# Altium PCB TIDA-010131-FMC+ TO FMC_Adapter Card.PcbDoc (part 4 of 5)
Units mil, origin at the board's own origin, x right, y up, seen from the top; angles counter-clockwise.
Board outline 2874.02 x 2362.2 mil, 12 copper layers (L1_Top Layer, L2_GND, L3_GND, L4_Signal layer1, L5_GND, L6_Signal Layer2, L7_GND, L8_Signal Layer3, L9_GND, L10_Signal Layer4, L11_GND, L12_Bottom Layer), stack 65.6 mil thick; 64 components, 219 nets, 2252 pads, 791 vias.
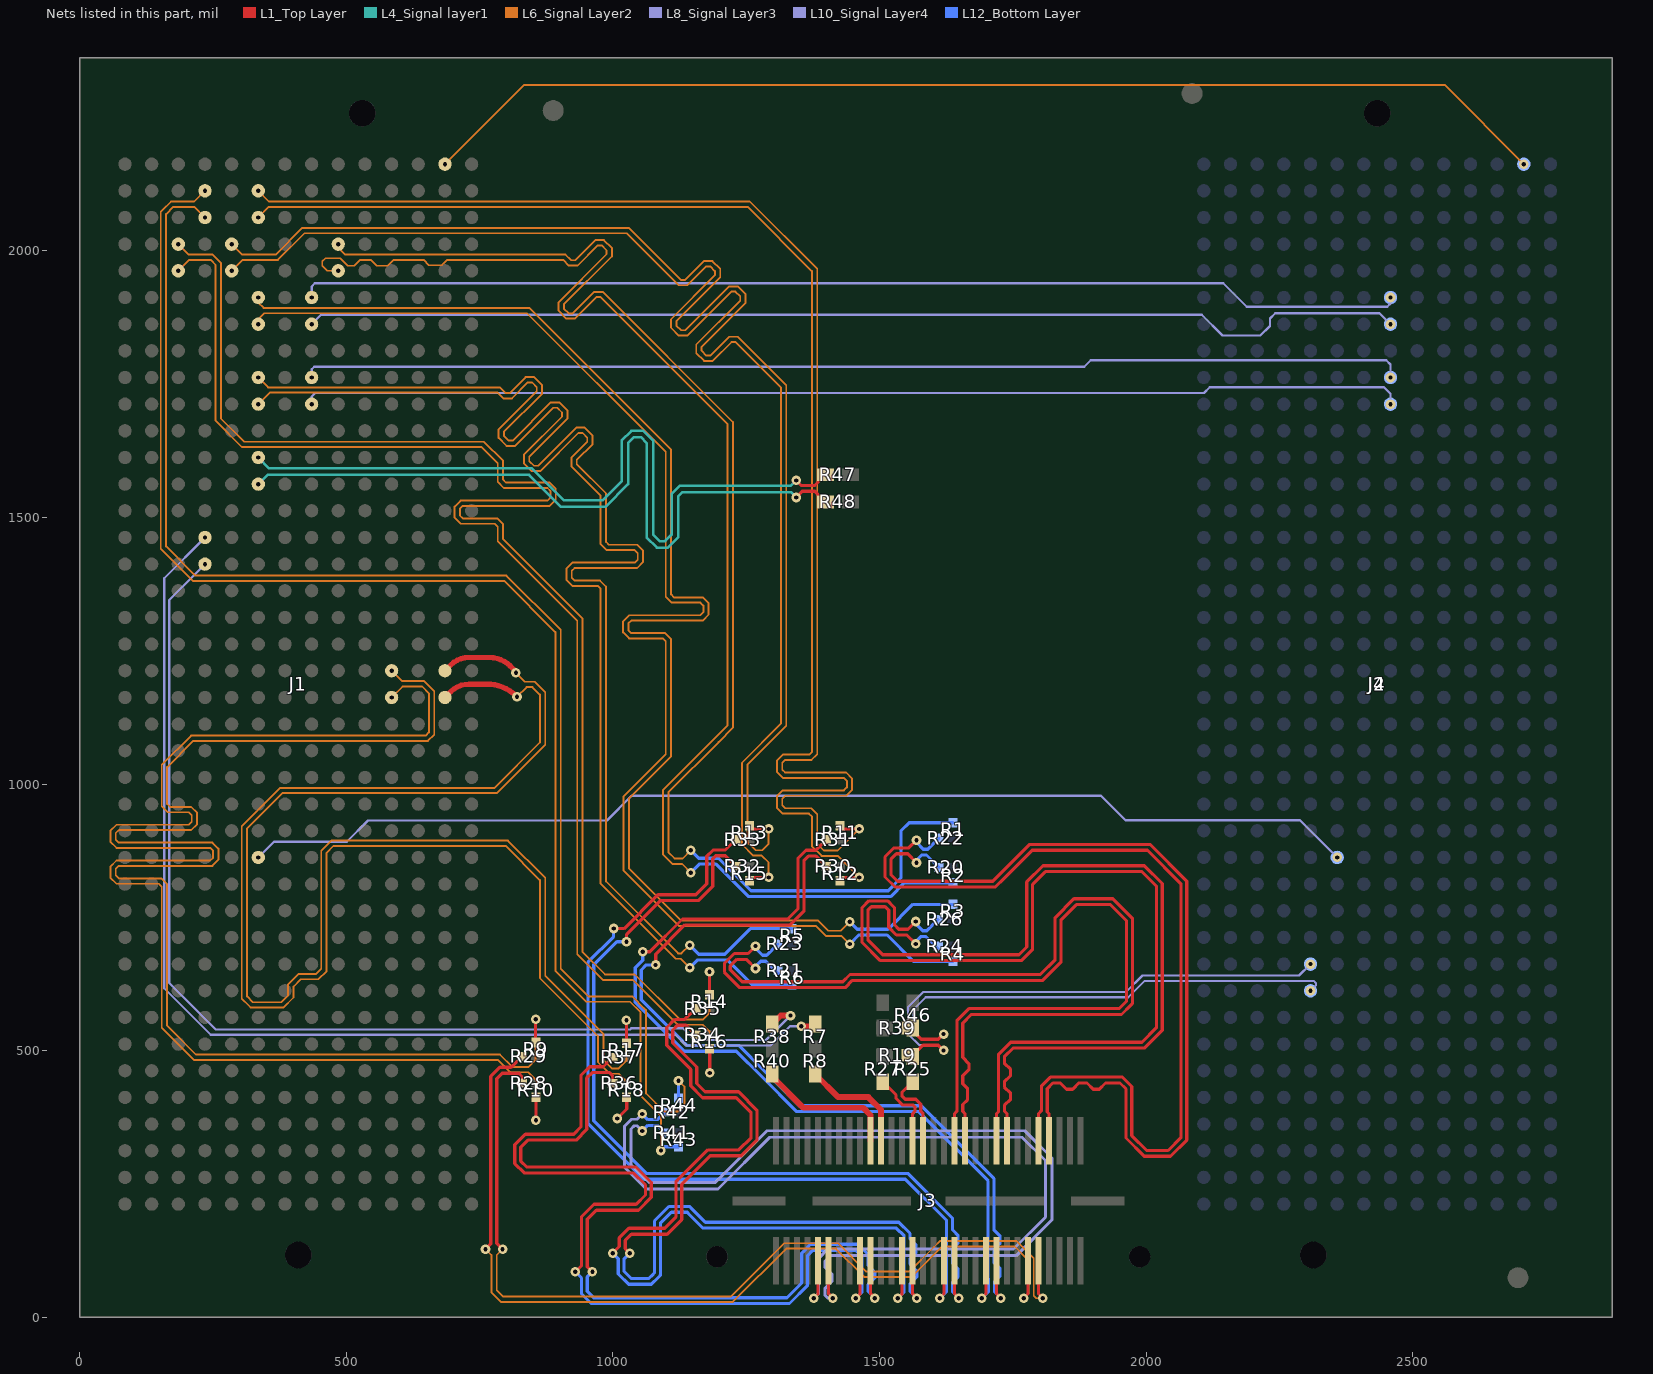
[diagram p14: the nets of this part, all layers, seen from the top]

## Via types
v1: diameter 18, hole 8, L1_Top Layer to L12_Bottom Layer, 791 vias

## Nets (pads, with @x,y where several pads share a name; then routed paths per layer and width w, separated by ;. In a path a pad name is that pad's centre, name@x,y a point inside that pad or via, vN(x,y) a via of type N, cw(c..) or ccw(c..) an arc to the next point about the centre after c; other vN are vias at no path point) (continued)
NetJ1_B20: J1.B20 R9.2 | length 2677.1
  L1_Top Layer w6: v1(855,559) 855,515.98 R9.2@855.49,515.48
  L6_Signal Layer2 w3.5: v1(585,1212.5) 604.5,1193 646.14,1193 665,1174.14 665,1092.86 653.14,1081 213,1081 164,1032 164,962.7 169.45,957.25 208.77,957.25 220.07,945.95 220.07,925.05 208.77,913.75 73.24,913.75 67.79,908.3 67.79,895.7 73.24,890.25 248.9,890.25 260.21,878.95 260.21,858.05 248.9,846.75 73.24,846.75 67.79,841.3 67.79,828.7 73.24,823.25 152.7,823.25 164,811.95 164,547 218,493 788,493 811.25,469.75 842,469.75 855,482.75 v1(855,559)
NetJ1_B21: J1.B21 R10.2 | length 2678.1
  L1_Top Layer w6: R10.2@855.01,413.01 R10.2@855.5,412.52 v1(855.5,369.49)
  L6_Signal Layer2 w3.5: v1(585,1162.5) 605.5,1183 642,1183 655,1170 655,1097 649,1091 208.86,1091 154,1036.14 154,958.55 165.3,947.25 204.63,947.25 210.07,941.8 210.07,929.2 204.63,923.75 69.1,923.75 57.79,912.45 57.79,891.55 69.1,880.25 244.76,880.25 250.21,874.8 250.21,862.2 244.76,856.75 69.1,856.75 57.79,845.45 57.79,824.55 69.1,813.25 148.55,813.25 154,807.8 154,542.86 213.86,483 783.86,483 807.11,459.75 841,459.75 855.5,445.25 v1(855.5,369.49)
NetJ1_D4: J1.D4 R1.2 | length 2678.3
  L6_Signal Layer2 w3.5: v1(485,2012.5) 485,2006 498,1993 911,1993 921.69,1982.31 929.4,1982.3 967.18,2020.09 983.17,2020.09 997.94,2005.32 997.94,1989.33 908,1899.39 908,1891.69 916.92,1882.77 924.62,1882.77 964.93,1923.08 980.92,1923.08 1225,1679 1225,1105.86 1198,1078.86 1104,984.86 1104,872 1115.5,860.5 1130.5,860.5 v1(1146,876)
  L12_Bottom Layer w6: v1(1146,876) 1161,861 1198,861 1258.94,800.06 1516.06,800.06 1540,824 1540,912 1555.52,927.52 R1.2@1637.75,927.52
NetJ1_D5: J1.D5 R2.2 | length 2675.8
  L6_Signal Layer2 w3.5: v1(485,1962.5) 464.5,1962.5 455,1972 455,1980 461,1986 489,1986 503,1972 515,1972 526,1983 546,1983 557,1972 578,1972 589,1983 645,1983 655,1973 679,1973 689,1983 906.86,1983 917.55,1972.31 933.54,1972.3 971.32,2010.09 979.02,2010.09 987.94,2001.17 987.94,1993.47 898,1903.53 898,1887.55 912.77,1872.77 928.76,1872.77 969.07,1913.08 976.77,1913.08 1215,1674.86 1215,1110 1094,989 1094,867.86 1111.36,850.5 1129.5,850.5 v1(1146,834)
  L12_Bottom Layer w6: v1(1146,834) 1162,850 1193.44,850 1254.39,789.06 1520.61,789.06 1546.6,815.04 R2.2@1637.75,815.04
NetJ1_G2: J1.G2 R11.1 | length 2680.8
  L1_Top Layer w6: R11.1@1426,922 1431.98,916.02 v1(1462.01,916.02)
  L6_Signal Layer2 w3.5: v1(335,2112.5) 355,2092.5 1256.64,2092.5 1383,1966.14 1383,1055.93 1372.32,1045.25 1322.87,1045.25 1317.42,1039.8 1317.42,1027.2 1322.87,1021.75 1437.27,1021.75 1448.58,1010.45 1448.58,989.55 1437.27,978.25 1322.87,978.25 1317.42,972.8 1317.42,960.2 1322.87,954.75 1371.7,954.75 1383,943.45 1383,888.02 1395.5,875.52 1421.51,875.52 v1(1462.01,916.02)
NetJ1_G3: J1.G3 R12.1 | length 2680.8
  L1_Top Layer w6: R12.1@1426,819.03 1431.98,825.02 v1(1462.01,825.02)
  L6_Signal Layer2 w3.5: v1(335,2062.5) 355,2082.5 1252.5,2082.5 1373,1962 1373,1060.07 1368.18,1055.25 1318.73,1055.25 1307.42,1043.95 1307.42,1023.05 1318.73,1011.75 1433.13,1011.75 1438.58,1006.3 1438.58,993.7 1433.13,988.25 1318.73,988.25 1307.42,976.95 1307.42,956.05 1318.73,944.75 1367.55,944.75 1373,939.3 1373,883.87 1391.36,865.52 1421.51,865.52 v1(1462.01,825.02)
NetJ1_G6: J1.G6 R3.1 | length 2675.3
  L6_Signal Layer2 w3.5: v1(335,1912.5) 335,1903 345,1893 843,1893 1109,1627 1109,1355.7 1114.45,1350.25 1168.2,1350.25 1179.5,1338.95 1179.5,1318.05 1168.2,1306.75 1034.45,1306.75 1029,1301.3 1029,1288.7 1034.45,1283.25 1097.7,1283.25 1109,1271.95 1109,1051.86 1030,972.86 1030,841.94 1127.94,744 1384.83,744 1403.83,725 1426.9,725 v1(1443.95,742.05)
  L12_Bottom Layer w6: v1(1443.95,742.05) 1458,728 1516,728 1562.49,774.49 R3.1@1637.6,774.49
NetJ1_G7: J1.G7 R4.1 | length 2677.3
  L6_Signal Layer2 w3.5: v1(335,1862.5) 335,1872 346,1883 838.86,1883 1099,1622.86 1099,1351.55 1110.3,1340.25 1164.06,1340.25 1169.5,1334.81 1169.5,1322.19 1164.06,1316.75 1030.3,1316.75 1019,1305.45 1019,1284.55 1030.3,1273.25 1093.55,1273.25 1099,1267.8 1099,1056 1020,977 1020,837.8 1123.8,734 1380.69,734 1399.69,715 1429,715 v1(1443.95,700.05)
  L12_Bottom Layer w6: v1(1443.95,700.05) 1460.9,717 1514,717 1563.39,667.61 R4.1@1637.6,667.61
NetJ1_G9: J1.G9 R5.1 | length 2676.2
  L6_Signal Layer2 w3.5: v1(335,1762.5) 353.5,1744 788.14,1744 798.84,1733.31 806.54,1733.3 836.35,1763.12 852.34,1763.12 867.11,1748.34 867.11,1732.36 795.64,1660.89 795.64,1653.19 804.56,1644.27 812.26,1644.27 883.73,1715.74 899.71,1715.74 914.49,1700.97 914.49,1684.98 843.02,1613.51 843.02,1605.81 851.93,1596.9 859.63,1596.9 931.1,1668.37 947.09,1668.37 961.86,1653.59 961.86,1637.61 932.05,1607.79 932.05,1600.09 987,1545.14 987,1454.2 992.45,1448.75 1045.15,1448.75 1056.45,1437.45 1056.45,1416.55 1045.15,1405.25 928.1,1405.25 922.65,1399.8 922.65,1387.2 928.1,1381.75 975.7,1381.75 987,1370.45 987,817.56 1122.06,682.5 1128.5,682.5 v1(1144,698)
  L12_Bottom Layer w6: v1(1144,698) 1161,681 1209.85,681 1257.82,728.97 R5.1@1335.93,728.97
NetJ1_G10: J1.G10 R6.1 | length 2676.1
  L6_Signal Layer2 w3.5: v1(335,1712.5) 356.5,1734 784,1734 794.69,1723.31 810.68,1723.3 840.49,1753.12 848.2,1753.12 857.11,1744.2 857.11,1736.5 785.64,1665.03 785.64,1649.05 800.41,1634.27 816.4,1634.27 887.87,1705.74 895.57,1705.74 904.49,1696.83 904.49,1689.12 833.02,1617.66 833.02,1601.67 847.79,1586.9 863.78,1586.9 935.25,1658.37 942.95,1658.37 951.86,1649.45 951.86,1641.75 922.05,1611.94 922.05,1595.95 977,1541 977,1450.05 988.3,1438.75 1041.01,1438.75 1046.45,1433.3 1046.45,1420.7 1041.01,1415.25 923.96,1415.25 912.65,1403.95 912.65,1383.05 923.96,1371.75 971.55,1371.75 977,1366.3 977,813.41 1117.91,672.5 1127.5,672.5 v1(1144,656)
  L12_Bottom Layer w6: v1(1144,656) 1158,670 1214.4,670 1214.7,670.3 1260.97,624.03 R6.1@1335.93,624.03
NetJ1_G12: J1.G12 R47.1 | length 1489.1
  L1_Top Layer w6: v1(1343.5,1569.5) 1353,1560 1378.38,1560 R47.1@1398.38,1580
  L4_Signal layer1 w4.9: v1(335,1612.5) 355.5,1592 848,1592 908,1532 980.74,1532 1016.45,1567.71 1016.45,1644.26 1034.69,1662.5 1057.11,1662.5 1075.35,1644.26 1075.35,1467.71 1087.56,1455.5 1098.04,1455.5 1110.25,1467.71 1110.25,1544.26 1125.49,1559.5 1333.5,1559.5 v1(1343.5,1569.5)
NetJ1_G13: J1.G13 R48.1 | length 1488.6
  L1_Top Layer w6: v1(1343.49,1537.5) 1354.99,1549 1378.38,1549 R48.1@1398.38,1529
  L4_Signal layer1 w4.9: v1(335,1562.5) 352.5,1580 843.03,1580 903.03,1520 985.71,1520 1028.45,1562.74 1028.45,1639.29 1039.66,1650.5 1052.14,1650.5 1063.35,1639.29 1063.35,1462.74 1082.59,1443.5 1103.01,1443.5 1122.25,1462.74 1122.25,1539.29 1130.46,1547.5 1333.49,1547.5 v1(1343.49,1537.5)
NetJ1_H4: J1.H4 R13.2 | length 2680
  L1_Top Layer w6: R13.2@1255.99,921.98 1261.98,916 v1(1292,916)
  L6_Signal Layer2 w3.5: v1(285,2012.5) 304.5,1993 367.44,1993 417.44,2043 1030,2043 1127.53,1945.47 1135.23,1945.47 1170.53,1980.77 1186.51,1980.77 1201.29,1966 1201.29,1950.01 1118.85,1867.57 1118.85,1859.87 1127.76,1850.95 1135.46,1850.95 1217.9,1933.39 1233.89,1933.39 1248.66,1918.62 1248.66,1902.63 1166.22,1820.19 1166.22,1812.49 1175.14,1803.58 1182.84,1803.58 1218.14,1838.88 1234.12,1838.88 1325,1748 1325,1109 1252,1036 1252,891.39 1267.39,876 1280,876 1292,888 v1(1292,916)
NetJ1_H5: J1.H5 R15.2 | length 2680.8
  L1_Top Layer w6: R15.2@1255.99,819.02 1261.98,825 v1(1292,825)
  L6_Signal Layer2 w3.5: v1(285,1962.5) 305.5,1983 371.59,1983 421.59,2033 1025.86,2033 1123.39,1935.47 1139.37,1935.47 1174.67,1970.77 1182.37,1970.77 1191.29,1961.85 1191.29,1954.15 1108.85,1871.71 1108.85,1855.73 1123.62,1840.95 1139.61,1840.95 1222.05,1923.39 1229.75,1923.39 1238.66,1914.48 1238.66,1906.78 1156.22,1824.34 1156.22,1808.35 1171,1793.58 1186.98,1793.58 1222.28,1828.88 1229.98,1828.88 1315,1743.86 1315,1113.14 1242,1040.14 1242,887.24 1263.24,866 1279,866 1292,853 v1(1292,825)
NetJ1_J2: J1.J2 R43.1 | length 2673.8
  L6_Signal Layer2 w3.5: v1(235,2112.5) 215,2092.5 171.36,2092.5 154.93,2076.07 152,2073.14 152,1441.5 212.5,1381 796,1381 892,1285 892,649.86 949.86,592 1032,592 1052,572 1052,415.86 1090,377.86 v1(1090,313)
  L12_Bottom Layer w6: v1(1090,313) 1097.02,320.02 R43.1@1122.98,320.02
NetJ1_J3: J1.J3 R44.1 | length 2673.8
  L6_Signal Layer2 w3.5: v1(235,2062.5) 215,2082.5 175.5,2082.5 162,2069 162,1445.64 216.64,1391 800.14,1391 902,1289.14 902,654 954,602 1036.14,602 1059.07,579.07 1062,576.14 1062,420 1096,386 1123,386 1134,397 1134,433 v1(1123,444)
  L12_Bottom Layer w6: R44.1@1122.98,410.98 v1(1123,444)
NetJ1_J15: J1.J15 R7.1 | length 2158.3
  L1_Top Layer w11: v1(1353,546) 1374.76,546 R7.1@1379,550.24
  L8_Signal Layer3 w4.25: v1(235,1462.5) 158.63,1386.13 158.63,617.37 246,530 1117,530 1137,510 1296,510 1332,546 v1(1353,546)
NetJ1_J16: J1.J16 R38.1 | length 2084
  L1_Top Layer w11: R38.1@1299,550.24 1314.76,566 v1(1333,566)
  L8_Signal Layer3 w4.25: v1(235,1412.5) 167.88,1345.38 167.88,627.12 255.15,539.85 1032.34,539.85 1034.49,542 1131,542 1153,520 1287,520 v1(1333,566)
NetJ1_K4: J1.K4 R14.2 | length 2676.7
  L1_Top Layer w6: R14.2@1181,604.98 v1(1181,648.01)
  L6_Signal Layer2 w3.5: v1(185,2012.5) 204.5,1993 249.56,1993 265,1977.56 265,1685.56 308.56,1642 758.14,1642 794,1606.14 794,1570.7 799.45,1565.25 881.43,1565.25 892.74,1553.95 892.74,1533.05 881.43,1521.75 718.46,1521.75 713.01,1516.3 713.01,1503.7 718.46,1498.25 782.7,1498.25 794,1486.95 794,1459.14 943,1310.14 943,685.14 985.14,643 1041,643 1125.25,558.75 1169,558.75 1181,570.75 v1(1181,648.01)
NetJ1_K5: J1.K5 R16.2 | length 2677.7
  L1_Top Layer w6: v1(1181.5,458.5) R16.2@1181.5,501.52
  L6_Signal Layer2 w3.5: v1(185,1962.5) 205.5,1983 245.41,1983 255,1973.41 255,1681.41 304.41,1632 754,1632 784,1602 784,1566.55 795.3,1555.25 877.29,1555.25 882.74,1549.8 882.74,1537.2 877.29,1531.75 714.32,1531.75 703.01,1520.45 703.01,1499.55 714.32,1488.25 778.55,1488.25 784,1482.8 784,1455 933,1306 933,681 981,633 1036.86,633 1121.1,548.75 1168,548.75 1181.5,535.25 v1(1181.5,458.5)
NetJ1_Z20: J1.Z20 R17.2 | length 2679.6
  L1_Top Layer w6: R17.2@1025.25,513.95 v1(1025.25,556.97)
  L1_Top Layer w10: J1.Z20@685,1212.5 695.86,1223.36 cw(c730,1189.22) 730,1237.5 768.17,1237.5 cw(c768.17,1181.17) 808,1221 818,1211 v1(818,1209)
  L6_Signal Layer2 w3.5: v1(818,1209) 835,1192 853,1192 873,1172 873,1073.86 782.14,983 380.14,983 314,916.86 314,602 325,591 378,591 391,604 391,624.28 410.72,644 419,644 443.36,644 453,653.64 453,875.14 471.86,894 803.14,894 873,824.14 873,640.56 982,531.56 982,483 998,467 1011,467 1025.25,481.25 v1(1025.25,556.97)
NetJ1_Z21: J1.Z21 R18.2 | length 2677.7
  L1_Top Layer w6: v1(1008,373) 1025.75,390.75 R18.2@1025.75,410.49
  L1_Top Layer w10: J1.Z21@685,1162.5 695.86,1173.36 cw(c730,1139.22) 730,1187.5 763.27,1187.5 cw(c763.27,1107.27) 792.37,1182.04 cw(c763.27,1107.27) v1(820,1164)
  L6_Signal Layer2 w3.5: v1(820,1164) 838,1182 848.86,1182 863,1167.86 863,1078 778,993 376,993 304,921 304,597.86 317.93,583.93 320.86,581 382.14,581 401,599.86 401,620.14 414.86,634 447.5,634 463,649.5 463,871 476,884 799,884 863,820 863,636.41 972,527.41 972,478.86 993.86,457 1011,457 1024,444 1024,389 v1(1008,373)
NetJ3_7: J3.7 R20.2 | length 1757.8
  L1_Top Layer w6: v1(1569.15,852.78) 1552.65,869.28 1531.53,869.28 1521.11,858.86 1521.11,830.45 1533.56,818 1712.41,818 1722.49,828.07 1781.41,887 2007,887 2076,818 2076,332.44 2045.56,302 1996.44,302 1962,336.44 1962,428.41 1950.86,439.56 1923.56,439.56 1912,428 1900.56,428 1889,439.56 1873.56,439.56 1862,428 1850.56,428 1839,439.56 1824.92,439.56 1814.36,429 1814.36,385.53 1817.71,382.18 J3.7@1817.71,331.5
  L12_Bottom Layer w6: v1(1569.15,852.78) 1569.15,856.93 1579.22,867 1587.94,867 R20.2@1611.16,843.78
NetJ3_9: J3.9 R22.2 | length 1756.9
  L1_Top Layer w6: v1(1569.15,894.78) 1554.65,880.28 1526.97,880.28 1510.11,863.42 1510.11,825.89 1529,807 1716.97,807 1733.49,823.51 1785.97,876 2002.44,876 2065,813.44 2065,337 2041,313 2001,313 1973,341 1973,432.97 1955.41,450.56 1820.36,450.56 1803.36,433.56 1803.36,387.53 1798.02,382.18 J3.9@1798.02,331.5
  L12_Bottom Layer w6: v1(1569.15,894.78) 1569.15,890.63 1581.78,878 1590.38,878 R22.2@1611.16,898.78
NetJ3_10: J3.10 R28.1 | length 1746.9
  L1_Top Layer w6: v1(793,128) 782,139 782,447.44 792.56,458 823.25,458 829.52,451.73 R28.1@829.52,439.5 ; J3.10@1798.02,105.91 1798.02,43.98 v1(1806,36)
  L6_Signal Layer2 w3.5: v1(793,128) 782,117 782,51 794,39 1220.86,39 1320.86,139 1422.14,139 1475.14,86 1556,86 1602,132 1613,143 1757.14,143 1789,111.14 1789,41 1794,36 v1(1806,36)
NetJ3_12: J3.12 R29.1 | length 1747.8
  L1_Top Layer w6: v1(761,128) 771,138 771,452 788,469 809.01,469 R29.1@829.51,489.5 ; v1(1770.36,36) 1778.34,43.98 J3.12@1778.34,105.91
  L6_Signal Layer2 w3.5: v1(761,128) 772,117 772,67.44 772,46.86 789.86,29 1225,29 1325,129 1418,129 1471,76 1560.14,76 1573.14,89 1617.14,133 1753,133 1779,107 1779,44.64 v1(1770.36,36)
NetJ3_15: J3.15 R24.2 | length 1742.7
  L1_Top Layer w6: v1(1567.59,700.35) 1550.94,717 1531.47,717 1517,731.47 1517,763.41 1513.49,766.93 1510.41,770 1484.59,770 1478,763.41 1478,708 1506,680 1761.41,680 1776,694.59 1776,816.56 1806.44,847 1996.56,847 2030,813.56 2030,538.44 1996.56,505 1750.21,505 1734.12,488.91 1734.12,476.43 1745.56,465 1745.56,453.56 1734.12,442.12 1734.12,431.93 1745.56,420.5 1745.56,409.06 1734.12,397.62 1734.12,387.03 1738.97,382.18 J3.15@1738.97,331.5
  L12_Bottom Layer w6: v1(1567.59,700.35) 1567.59,704.5 1577.09,714 1586.96,714 R24.2@1609.61,691.35
NetJ3_17: J3.17 R26.2 | length 1741.6
  L1_Top Layer w6: v1(1567.59,742.35) 1553.24,728 1536.03,728 1528,736.03 1528,767.97 1524.49,771.49 1514.97,781 1480.03,781 1467,767.97 1467,703.44 1501.44,669 1765.97,669 1787,690.03 1787,812 1811,836 1992,836 2019,809 2019,543 1992,516 1745.65,516 1723.12,493.47 1723.12,386.03 1719.28,382.18 J3.17@1719.28,331.5
  L12_Bottom Layer w6: v1(1567.59,742.35) 1567.59,738.2 1580.8,725 1588.26,725 R26.2@1609.61,746.35
NetJ3_18: J3.18 R30.1 | length 1688.2
  L1_Top Layer w6: v1(1080,661) 1080.28,661.28 1080.28,681.28 1135,736 1332.56,736 1358,761.44 1358,856.44 1366.56,865 1381.03,865 R30.1@1400.02,846.02 ; J3.18@1719.28,105.91 1719.28,43.98 v1(1727.26,36)
  L12_Bottom Layer w6: v1(1080,661) 1062.57,661 1053,651.43 1053,595.59 1138.59,510 1236,510 1283.28,462.72 1349,397 1578,397 1714.44,260.56 1714.44,164 1726,152.44 1726,138.56 1714.44,127 1714.44,103 1726,91.44 1726,77.56 1715.44,67 1715.44,47.82 v1(1727.26,36)
NetJ3_20: J3.20 R31.1 | length 1686.6
  L1_Top Layer w6: v1(1055.78,685.78) 1069.28,685.78 1069.28,685.83 1130.44,747 1328,747 1347,766 1347,861 1362,876 1380,876 R31.1@1400.02,896.02 ; v1(1691.62,36) 1699.6,43.98 J3.20@1699.6,105.91
  L12_Bottom Layer w6: v1(1055.78,685.78) 1055.78,669.76 1042,655.99 1042,591.03 1134.03,499 1231.44,499 1278.72,451.72 1344.44,386 1573.44,386 1703.44,256.01 1703.44,72.56 1704.44,71.56 1704.44,48.82 v1(1691.62,36)
NetJ3_23: J3.23 R21.2 | length 1747.9
  L1_Top Layer w6: v1(1267.3,654.23) 1250.15,671.37 1232.35,671.37 1220,659.03 1220,652 1232.22,639.78 1242.51,629.49 1430.93,629.49 1444.44,643 1801.44,643 1829,670.56 1829,749.56 1864.44,785 1937.56,785 1974,748.56 1974,588.44 1970.78,585.22 1953.56,568 1672,568 1655.88,551.88 1655.88,487.56 1667.44,476 1667.44,464.56 1655.88,453 1655.88,438.12 1665,429 1665,408.4 1655.88,399.28 1655.88,386.53 1660.23,382.18 J3.23@1660.23,331.5
  L12_Bottom Layer w6: v1(1267.3,654.23) 1267.3,658.38 1276.92,668 1286.54,668 R21.2@1309.31,645.23
NetJ3_25: J3.25 R23.2 | length 1748.5
  L1_Top Layer w6: v1(1267.3,696.23) 1253.44,682.37 1227.79,682.37 1209,663.59 1209,647.44 1221.22,635.22 1237.96,618.49 1435.49,618.49 1449,632 1806,632 1840,666 1840,745 1869,774 1933,774 1963,744 1963,593 1949,579 1667.44,579 1644.88,556.44 1644.88,386.53 1640.54,382.18 J3.25@1640.54,331.5
  L12_Bottom Layer w6: v1(1267.3,696.23) 1267.3,692.08 1280.38,679 1288.08,679 R23.2@1309.31,700.23
NetJ3_26: J3.26 R32.1 | length 1683.6
  L1_Top Layer w6: v1(1025.5,704.5) 1025.5,718.12 1088.95,781.57 1160.12,781.57 1187,808.44 1187,860 1192.5,865.5 1210.51,865.5 R32.1@1230.01,846 ; J3.26@1640.54,105.91 1640.54,43.98 v1(1648.52,36)
  L12_Bottom Layer w6: v1(1025.5,704.5) 1007.36,704.5 964,661.14 964,368.56 1062.56,270 1553,270 1636.7,186.3 1636.7,164 1647.26,153.44 1647.26,139.56 1636.7,129 1636.7,101 1647.26,90.44 1647.26,76.56 1636.7,66 1636.7,47.82 v1(1648.52,36)
NetJ3_28: J3.28 R33.1 | length 1686
  L1_Top Layer w6: v1(1001.28,729.28) 1001.56,729 1020.83,729 1084.39,792.57 1155.57,792.57 1176,813 1176,864.56 1187.94,876.5 1210.51,876.5 R33.1@1230.01,896 ; v1(1612.88,36) 1620.86,43.98 J3.28@1620.86,105.91
  L12_Bottom Layer w6: v1(1001.28,729.28) 1001.28,713.97 953,665.69 953,364 1058,259 1548.44,259 1625.7,181.75 1625.7,48.82 v1(1612.88,36)
NetJ3_31: J3.31 R25.2 | length 147
  L1_Top Layer w6: R25.2@1562,442 1541.75,421.75 1541.75,415.37 1548.12,409 1568,409 1577.14,399.86 1577.14,386.53 1581.48,382.18 J3.31@1581.48,331.5
NetJ3_33: J3.33 R27.2 | length 158.9
  L1_Top Layer w6: R27.2@1506,442 1530.75,417.25 1530.75,410.82 1543.57,398 1563.44,398 1566.14,395.3 1566.14,386.53 1561.8,382.18 J3.33@1561.8,331.5
  L1_Top Layer w11: R27.2@1506,431.99 R27.2@1506,442
NetJ3_34: J3.34 R34.1 | length 1688.5
  L1_Top Layer w6: v1(1031.5,120.5) 1023,129 1023,144.44 1034.56,156 1101.56,156 1129,183.44 1129,249.44 1182.56,303 1240.56,303 1270,332.44 1270,388.56 1235.56,423 1172.56,423 1157,438.56 1157,469.56 1112,514.56 1112,539 1120.75,547.75 1137.26,547.75 R34.1@1155.02,530 ; J3.34@1561.8,105.91 1561.8,43.98 v1(1569.78,36)
  L12_Bottom Layer w6: v1(1031.5,120.5) 1021,110 1021,86 1034,73 1067.41,73 1074.49,80.07 1078,83.59 1078,181 1105,208 1143.97,208 1147.97,204 1173.46,178.51 1536.04,178.51 1556.96,157.6 1556.96,147 1568.52,135.44 1568.52,121.56 1556.96,110 1556.96,100 1570,86.96 1570,76.04 1556.96,63 1556.96,48.82 v1(1569.78,36)
NetJ3_36: J3.36 R35.1 | length 1688.6
  L1_Top Layer w6: v1(999.5,120.5) 1012,133 1012,149 1030,167 1097,167 1118,188 1118,254 1178,314 1236,314 1259,337 1259,384 1231,412 1168,412 1146,434 1146,465 1101,510 1101,543.56 1116.2,558.75 1134.77,558.75 R35.1@1155.02,579 ; v1(1534.14,36) 1542.11,43.98 J3.36@1542.11,105.91
  L12_Bottom Layer w6: v1(999.5,120.5) 1010,110 1010,81.44 1029.44,62 1071.97,62 1085.49,75.51 1089,79.03 1089,176.44 1109.56,197 1139.41,197 1143.41,193 1168.9,167.51 1531.49,167.51 1545.96,153.04 1545.96,47.82 v1(1534.14,36)
NetJ3_39: J3.39 R8.2 | length 209.2
  L1_Top Layer w11: R8.2@1379,456.24 1422.24,413 1479,413 1502.74,389.26 J3.39@1502.74,331.5
NetJ3_41: J3.41 R40.2 | length 266.7
  L1_Top Layer w11: R40.2@1299,456.24 1299,451 1357,393 1469.24,393 1483.06,379.18 J3.41@1483.06,331.5
NetJ3_42: J3.42 R36.1 | length 1697.9
  L1_Top Layer w6: v1(961.5,85.5) 952,95 952,184 969,201 1048,201 1072,225 1072,253 1043,282 838,282 827,293 827,319 840.49,332.49 931.04,332.49 951,352.44 951,449 961,459 993.71,459 999.26,453.45 R36.1@999.26,438.96 ; J3.42@1483.06,105.91 1483.06,43.98 v1(1491.04,36)
  L12_Bottom Layer w6: v1(961.5,85.5) 952,76 952,49 964,37 1326.44,37 1353.95,64.51 1353.95,120.56 1370.39,137 1459.56,137 1478.22,118.34 1478.22,97.78 1491.04,84.96 1491.04,74.04 1479,62 ; v1(1491.04,36) 1479.22,47.82 ; 1479,62 1478.22,61.22 1478.22,48.82 1479.22,47.82 ; 1479,62 1479.22,47.82
NetJ3_44: J3.44 R37.1 | length 1683.2
  L1_Top Layer w6: v1(929.5,85.5) 941,97 941,188.56 964.44,212 1043.44,212 1061,229.56 1061,248.44 1038.44,271 833.44,271 816,288.44 816,323.56 835.93,343.49 926.49,343.49 940,357 940,453.56 956.44,470 981.3,470 R37.1@999.26,487.96 ; v1(1455.4,36) 1463.37,43.98 J3.44@1463.37,105.91
  L12_Bottom Layer w6: v1(929.5,85.5) 941,74 941,44.44 959.44,26 1331,26 1364.95,59.95 1364.95,116 1374.95,126 1455,126 1467.22,113.78 1467.22,47.82 v1(1455.4,36)
NetJ3_50: J3.50 R41.1 | length 1749.4
  L1_Top Layer w6: J3.50@1404.32,105.91 1404.32,43.98 v1(1412.3,36)
  L10_Signal Layer4 w5.5: v1(1054.96,349.5) 1045.06,359.4 1040,359.4 1034,353.4 1034,286.65 1067.65,253 1192,253 1289,350 1772.25,350 1823.2,299.05 1823.2,182.95 1756.05,115.8 1660.05,115.8 1575.05,115.8 1407.8,115.8 1398,106 1398,94 1411,81 1411,67.68 1398,54.68 1398,41 1403,36 v1(1412.3,36)
  L12_Bottom Layer w6: v1(1054.96,349.5) 1065.46,360 1083,360 R41.1@1097,346
NetJ3_52: J3.52 R42.1 | length 1751.3
  L1_Top Layer w6: v1(1376.65,36) 1384.63,43.98 J3.52@1384.63,105.91
  L10_Signal Layer4 w5.5: v1(1054.96,381.5) 1045.06,371.6 1034.95,371.6 1021.8,358.45 1021.8,281.6 1062.6,240.8 1197.05,240.8 1294.05,337.8 1767.2,337.8 1811,294 1811,188 1751,128 1402.75,128 1385.8,111.05 1385.8,45.14 v1(1376.65,36)
  L12_Bottom Layer w6: v1(1054.96,381.5) 1065.46,371 1083,371 R42.1@1097,385
OVRA0: J1.G27 J2.G27 J4.G27 | length 2118.7
  L8_Signal Layer3 w4.25: v1(335,862.5) 364.5,892 501,892 540.75,931.75 988.75,931.75 1035,978 1915,978 1961,932 2288.5,932 v1(2358,862.5)
SYNC_SE_IN: J2.H31 J4.H31 R19.2 R25.1 | length 990.6
  L1_Top Layer w6: R19.2@1560,489.24 1581.19,510.43 1610.2,510.43 v1(1620,500.63)
  L8_Signal Layer3 w4: v1(1620,500.63) 1609.7,510.93 1574.17,510.93 1555.93,529.17 1553,532.1 1553,581.04 1555.93,583.97 1582.36,610.4 1962.4,610.4 1993,641 2286.5,641 v1(2308,662.5)
SYNC_SE_IN_N: J2.H32 J4.H32 R39.2 R46.2 | length 982.2
  L1_Top Layer w6: R39.2@1556.62,542.62 1577.81,521.43 1610.2,521.43 v1(1620,531.23)
  L8_Signal Layer3 w4: v1(1620,531.23) 1609.7,520.93 1578.31,520.93 1563,536.24 1563,576.9 1586.5,600.4 1966.54,600.4 1997.14,631 2314,631 2318,627 2318,622.5 v1(2308,612.5)
SYNCB0CMOS: J1.E6 J2.E6 J4.E6 | length 2078.2
  L8_Signal Layer3 w4.25: v1(435,1912.5) 435,1933 441,1939 2144.58,1939 2188.58,1895 2452,1895 2458,1901 v1(2458,1912.5)
SYNCB1CMOS: J1.E7 J2.E7 J4.E7 | length 2080.5
  L8_Signal Layer3 w4.25: v1(435,1862.5) 452.5,1880 2104,1880 2143,1841 2214,1841 2232,1859 2232,1873 2242,1883 2437.5,1883 v1(2458,1862.5)
SYNCB2CMOS: J1.E9 J2.E9 J4.E9 | length 2073.4
  L8_Signal Layer3 w4.25: v1(435,1762.5) 435,1778 439.75,1782.75 1883.75,1782.75 1896,1795 2450,1795 2458,1787 v1(2458,1762.5)
SYNCB3CMOS: J1.E10 J2.E10 J4.E10 | length 2069
  L8_Signal Layer3 w4.25: v1(435,1712.5) 435,1727 441.25,1733.25 2108.25,1733.25 2119,1744 2446,1744 2458,1732 v1(2458,1712.5)
Z1: J1.Z1 J4.Z1 | length 2146
  L6_Signal Layer2 w3.75: v1(685,2162.5) 833.5,2311 2559.5,2311 v1(2708,2162.5)
pads on no net: FID1.1 FID2.1 FID3.1 J1. J1.B1 J1.B40 J1.C10 J1.C11 J1.C19 J1.C22 J1.C23 J1.C26 J1.C27 J1.D8 J1.D9 J1.D20 J1.D21 J1.D22 J1.D23 J1.D24 J1.E2 J1.E3 J1.E18 J1.E19 J1.E20 J1.E21 J1.E22 J1.E24 J1.E25 J1.E27 J1.E28 J1.E30 J1.E31 J1.E33 J1.E34 J1.E36 J1.E37 J1.F2 J1.F4 J1.F5 J1.F7 J1.F8 J1.F22 J1.F23 J1.F25 J1.F26 J1.F28 J1.F29 J1.F31 J1.F32 J1.F34 J1.F35 J1.F37 J1.F38 J1.G19 J1.G22 J1.G24 J1.G25 J1.G28 J1.G30 J1.G31 J1.G33 J1.G34 J1.G36 J1.G37 J1.H7 J1.H8 J1.H10 J1.H11 J1.H13 J1.H14 J1.H20 J1.H22 J1.H23 J1.H25 J1.H26 J1.H34 J1.H35 J1.H37 J1.H38 J1.J21 J1.J22 J1.J24 J1.J25 J1.J27 J1.J28 J1.J30 J1.J31 J1.J33 J1.J34 J1.J36 J1.J37 J1.K16 J1.K17 J1.K18 J1.K19 J1.K20 J1.K21 J1.K22 J1.K23 J1.K24 J1.K25 J1.K26 J1.K27 J1.K28 J1.K29 J1.K31 J1.K32 J1.K34 J1.K35 J1.K37 J1.K38 J1.L1 J1.L2 J1.L3 J1.L4 J1.L5 J1.L6 J1.L8 J1.L9 J1.L10 J1.L11 J1.L12 J1.L13 J1.L14 J1.L15 J1.L16 J1.L17 J1.L18 J1.L19 J1.L20 J1.L21 J1.L22 J1.L23 J1.L24 J1.L25 J1.L26 J1.L27 J1.L28 J1.L29 J1.L32 J1.L33 J1.L36 J1.L37 J1.L40 J1.M2 J1.M3 J1.M4 J1.M5 J1.M6 J1.M7 J1.M8 J1.M9 J1.M10 J1.M11 J1.M12 J1.M13 J1.M14 J1.M15 J1.M16 J1.M17 J1.M18 J1.M19 J1.M20 J1.M21 J1.M22 J1.M23 J1.M24 J1.M25 J1.M26 J1.M27 J1.M28 J1.M30 J1.M31 J1.M34 J1.M35 J1.M38 J1.M39 J1.Y1 J1.Y2 J1.Y3 J1.Y34 J1.Y35 J1.Y38 J1.Y39 J1.Z4 J1.Z5 J1.Z6 J1.Z32 J1.Z33 J1.Z36 J1.Z37 J1.Z40 J2.B1 J2.B2 J2.B40 J2.C10 J2.C11 J2.C19 J2.C22 J2.C23 J2.C26 J2.C27 J2.D8 J2.D9 J2.D20 J2.D21 J2.D22 J2.D23 J2.D24 J2.E2 J2.E3 J2.E18 J2.E19 J2.E20 J2.E21 J2.E22 J2.E24 J2.E25 J2.E27 J2.E28 J2.E30 J2.E31 J2.E33 J2.E34 J2.E36 J2.E37 J2.F2 J2.F4 J2.F5 J2.F7 J2.F8 J2.F22 J2.F23 J2.F25 J2.F26 J2.F28 J2.F29 J2.F31 J2.F32 J2.F34 J2.F35 J2.F37 J2.F38 J2.G19 J2.G22 J2.G24 J2.G25 J2.G28 J2.G30 J2.G31 J2.G33 J2.G34 J2.G36 J2.G37 J2.H7 J2.H8 J2.H10 J2.H11 J2.H13 J2.H14 J2.H20 J2.H22 J2.H23 J2.H25 J2.H26 J2.H34 J2.H35 J2.H37 J2.H38 J2.J21 J2.J22 J2.J24 J2.J25 J2.J27 J2.J28 J2.J30 J2.J31 J2.J33 J2.J34 J2.J36 J2.J37 J2.K16 J2.K17 J2.K18 J2.K19 J2.K20 J2.K21 J2.K22 J2.K23 J2.K24 J2.K25 J2.K26 J2.K27 J2.K28 J2.K29 J2.K31 J2.K32 J2.K34 J2.K35 J2.K37 J2.K38 J2.MH1 J2.MH2 J3.1 J3.2 J3.4 J3.60 J3.MH1 J3.MH2 J4.B1 J4.B2 J4.B40 J4.C10 J4.C11 J4.C19 J4.C22 J4.C23 J4.C26 J4.C27 J4.D8 J4.D9 J4.D20 J4.D21 J4.D22 J4.D23 J4.D24 J4.E2 J4.E3 J4.E18 J4.E19 J4.E20 J4.E21 J4.E22 J4.E24 J4.E25 J4.E27 J4.E28 J4.E30 J4.E31 J4.E33 J4.E34 J4.E36 J4.E37 J4.F2 J4.F4 J4.F5 J4.F7 J4.F8 J4.F22 J4.F23 J4.F25 J4.F26 J4.F28 J4.F29 J4.F31 J4.F32 J4.F34 J4.F35 J4.F37 J4.F38 J4.G19 J4.G22 J4.G24 J4.G25 J4.G28 J4.G30 J4.G31 J4.G33 J4.G34 J4.G36 J4.G37 J4.H7 J4.H8 J4.H10 J4.H11 J4.H13 J4.H14 J4.H20 J4.H22 J4.H23 J4.H25 J4.H26 J4.H34 J4.H35 J4.H37 J4.H38 J4.J21 J4.J22 J4.J24 J4.J25 J4.J27 J4.J28 J4.J30 J4.J31 J4.J33 J4.J34 J4.J36 J4.J37 J4.K16 J4.K17 J4.K18 J4.K19 J4.K20 J4.K21 J4.K22 J4.K23 J4.K24 J4.K25 J4.K26 J4.K27 J4.K28 J4.K29 J4.K31 J4.K32 J4.K34 J4.K35 J4.K37 J4.K38 J4.L1 J4.L2 J4.L3 J4.L4 J4.L5 J4.L6 J4.L8 J4.L9 J4.L10 J4.L11 J4.L12 J4.L13 J4.L14 J4.L15 J4.L16 J4.L17 J4.L18 J4.L19 J4.L20 J4.L21 J4.L22 J4.L23 J4.L24 J4.L25 J4.L26 J4.L27 J4.L28 J4.L29 J4.L32 J4.L33 J4.L36 J4.L37 J4.L40 J4.M2 J4.M3 J4.M4 J4.M5 J4.M6 J4.M7 J4.M8 J4.M9 J4.M10 J4.M11 J4.M12 J4.M13 J4.M14 J4.M15 J4.M16 J4.M17 J4.M18 J4.M19 J4.M20 J4.M21 J4.M22 J4.M23 J4.M24 J4.M25 J4.M26 J4.M27 J4.M28 J4.M30 J4.M31 J4.M34 J4.M35 J4.M38 J4.M39 J4.MH1 J4.MH2 J4.Y1 J4.Y2 J4.Y3 J4.Y34 J4.Y35 J4.Y38 J4.Y39 J4.Z4 J4.Z5 J4.Z6 J4.Z32 J4.Z33 J4.Z36 J4.Z37 J4.Z40 LBL1.0

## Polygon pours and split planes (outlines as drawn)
GND on L1_Top Layer "Bottom Layer-No Net" (solid, remove dead copper, pour order 26): 1876,272 1238,272 1224,258 1218,252 1218,218 1218,183 1222,179 1229,172 1548,172 1956,172 1966,182 1966,262 1956,272
GND on L2_GND "GND_L02_P018" (solid, remove dead copper, pour order 18): 0,2362.2 119.2,2362.2 0,2243 0,132.5 132.5,0 2740,0 2877,137 2877,2239 2753.23,2362.77
GND on L11_GND "GND_L05_P024" (solid, remove dead copper, pour order 24): 0,2362.2 119.2,2362.2 0,2243 0,132.5 132.5,0 2740,0 2877,137 2877,2239 2753.23,2362.77
GND on L3_GND "GND_L02_P018" (solid, remove dead copper, pour order 28): 0,2362.2 119.2,2362.2 0,2243 0,132.5 132.5,0 2740,0 2877,137 2877,2239 2753.23,2362.77
GND on L5_GND "GND_L02_P018" (solid, remove dead copper, pour order 30): 0,2362.2 119.2,2362.2 0,2243 0,132.5 132.5,0 2740,0 2877,137 2877,2239 2753.23,2362.77
GND on L7_GND "GND_L02_P018" (solid, remove dead copper, pour order 32): 0,2362.2 119.2,2362.2 0,2243 0,132.5 132.5,0 2740,0 2877,137 2877,2239 2753.23,2362.77
GND on L9_GND "GND_L02_P018" (solid, remove dead copper, pour order 34): 0,2362.2 119.2,2362.2 0,2243 0,132.5 132.5,0 2740,0 2877,137 2877,2239 2753.23,2362.77

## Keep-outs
Keep-Out Layer:
  circle w10: c2313,117 r30
  circle w10: c2433,2257.97 r30
  circle w10: c530,2258 r30
  circle w10: c410,117 r30
  circle w10: c1195.07,113.59 r25.1
  circle w10: c1987.59,113.59 r25.1
  text ".Layer_Name" at -4846.13,-1935.49 h60

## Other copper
L1_Top Layer:
  text "'.Layer_Name'" at -4737,-1916 h60
L2_GND:
  pour cut-out: 1342.19,535.19 1335,528 1335,525 1347,525 1352.71,530.71 1350.07,530.71 1345.59,535.19
  text "'.Layer_Name'" at -4833,-1936 h60
L11_GND:
  pour cut-out: 1342.19,535.19 1335,528 1335,525 1347,525 1352.71,530.71 1350.07,530.71 1345.59,535.19
  text "'.Layer_Name'" at -4832,-1932 h60
L6_Signal Layer2:
  text "'.Layer_Name'" at -4819,-1938 h60
L8_Signal Layer3:
  text "'.Layer_Name'" at -4772,-1938 h60
L3_GND:
  pour cut-out: 1342.19,535.19 1335,528 1335,525 1347,525 1352.71,530.71 1350.07,530.71 1345.59,535.19
  text "'.Layer_Name'" at -4704,-1939 h60
L4_Signal layer1:
  text "'.Layer_Name'" at -4761,-1946 h60
L5_GND:
  pour cut-out: 1342.19,535.19 1335,528 1335,525 1347,525 1352.71,530.71 1350.07,530.71 1345.59,535.19
  text "'.Layer_Name'" at -4751,-1932 h60
L7_GND:
  pour cut-out: 1342.19,535.19 1335,528 1335,525 1347,525 1352.71,530.71 1350.07,530.71 1345.59,535.19
  text "'.Layer_Name'" at -4741,-1944 h60
L9_GND:
  pour cut-out: 1342.19,535.19 1335,528 1335,525 1347,525 1352.71,530.71 1350.07,530.71 1345.59,535.19
  text "'.Layer_Name'" at -4739,-1941 h60
L10_Signal Layer4:
  text "'.Layer_Name'" at -4708,-1951 h60
L12_Bottom Layer:
  text "'.Layer_Name'" at -4674,-1936 h60

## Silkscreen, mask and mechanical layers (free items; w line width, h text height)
Top Overlay:
  text "TIDA-010131_FMC+ TO FMC CARD_E3" at 1122,2280 h30
  text "TOP OVERLAY" at -4846.13,-1935.49 h50
Bottom Overlay:
  rectangle: 2842,2151 2854,2174
  text "BOTTOM OVERLAY" at -4731.9,-1949 h50
Top Paste:
  text "TOP PASTE" at -4846.13,-1935.49 h60
Bottom Paste:
  text "BOTTOM PASTE" at -4846.13,-1935.49 h60
Top Solder:
  text "TOP SOLDER" at -4846.13,-1935.49 h60
Bottom Solder:
  text "BOTTOM SOLDER" at -4846.13,-1935.49 h60
Drill Guide:
  text ".Layer_Name" at -4846.13,-1935.49 h60
M1 Board Outline:
  the board outline again, w10
M2 Board Dimensions:
  rectangle: -5423.63,-1362.5 -5298.63,-1237.5
  rectangle: -5298.63,-1487.5 -4923.63,-1362.5
  lines w7: -5423.63,-1362.5 -4423.63,-1362.5 ; -5298.63,-1487.5 -5298.63,-1237.5 ; -5173.63,-1487.5 -5173.63,-1237.5 ; -4923.63,-1487.5 -4923.63,-1237.5 ; -4673.63,-1487.5 -4673.63,-1237.5 ; -5423.63,-1487.5 -4423.63,-1487.5 -4423.63,-1237.5 -5423.63,-1237.5 -5423.63,-1487.5
  lines w10: -5423.63,-1552.5 -5423.63,-1532.5 ; -5363.63,-1562.5 -5423.63,-1542.5 ; -5363.63,-1522.5 -5423.63,-1542.5 ; -5199.54,-1542.5 -5423.63,-1542.5 ; -4647.71,-1542.5 -4423.63,-1542.5 ; -4483.63,-1562.5 -4423.63,-1542.5 ; -4483.63,-1522.5 -4423.63,-1542.5 ; -4423.63,-1552.5 -4423.63,-1532.5
  text "1000 (mil)" at -5189.54,-1578.49 h60
M3 3D STEP Top:
  text ".Layer_Name" at -4846.13,-1935.49 h60
M4 3D STEP Bottom:
  text ".Layer_Name" at -4846.13,-1935.49 h60
M5 Assembly Top:
  circle w10: c805,2155 r13.46
  circle w10: c1881,320 r10
  lines w10: -5715.13,-2007.17 884.87,-2007.17 ; -5715.13,-1803.83 886.87,-1803.83 ; -5715.13,-1600.5 -5715.13,-2210.5 -1710.13,-2210.5 886.87,-2210.5 886.87,-1600.5 -5714.63,-1600.5 -5714.63,-2210.5 -4139.13,-2210.5 ; -3250.13,-2210.5 -3250.13,-1600.5 ; -1983.13,-1803.83 -1983.13,-1600.5 ; -1143.13,-1803.83 -1143.13,-1600.5 ; -521.13,-2217 -521.13,-2014.17
  text "COMPONENTS MARKED 'DNP' SHOULD NOT BE POPULATED." at -4269.63,-1395.5 h60
  text "ASSEMBLY VARIANT:" at -4270.13,-1511 h60
  text ".VariantName" at -3234.13,-1511 h60
  text "PCB VIEWED FROM TOP SIDE" at -5651.63,-1732.67 h60
  text "BOARD #:" at -3175.13,-1732.67 h60
  text "'.PRJ_Number'" at -2677,-1733 h60
  text "REV:" at -1785.13,-1732.67 h60
  text "SVN REV:" at -947.13,-1732.67 h60
  text "'.PCB_Rev'" at -1514,-1735 h60
  text "TID #:" at -3175.13,-1928.67 h60
  text "ASSEMBLY TOP" at -4839.9,-1930 h60
  text "LAYER NAME =" at -5651.63,-1935.49 h60
  text "010131" at -2822,-1935 h60
  text ".plot_File_Name" at -4987,-2128 h35
  text "PLOT NAME =" at -5651.63,-2141.34 h60
  text "GENERATED    :" at -3173.13,-2141.34 h60
  text ".Print_Date" at -2303.63,-2141.34 h60
  text ".Print_Time" at -1574.63,-2141.34 h60
  text "TEXAS INSTRUMENTS" at -310.13,-2141.34 h60
M6 Assembly Bottom:
  circle w10: c2658,2165.5 r15.81
  lines w10: -5715.63,-1804.33 886.37,-1804.33 ; -5713.63,-2007.67 886.37,-2007.67 ; -4307.63,-2217.5 -4307.63,-2014.67 ; -3685.63,-1804.33 -3685.63,-1601 ; -2845.63,-1804.33 -2845.63,-1601 ; -1578.63,-2211 -1578.63,-1601 ; -689.63,-2211 885.87,-2211 885.87,-1601 -5715.63,-1601 -5715.63,-2211 -3118.63,-2211 886.37,-2211 886.37,-1601
  text "J2" at 2472.09,1337.5 h25
  text "COMPONENTS MARKED 'DNP' SHOULD NOT BE POPULATED." at 678.87,-1395 h60
  text ".VariantName" at -365.13,-1511 h60
  text "ASSEMBLY VARIANT:" at 673.87,-1511 h60
  text "SVN REV:" at -3881.63,-1733.17 h60
  text "REV:" at -3043.63,-1733.17 h60
  text "'.PRJ_Number'" at -2199.13,-1733.17 h60
  text "BOARD #:" at -1653.63,-1733.17 h60
  text "PCB VIEWED FROM BOTTOM SIDE" at 822.87,-1733.17 h60
  text "'.PCB_Rev'" at -3319,-1735 h60
  text "ASSEMBLY BOTTOM" at -186,-1917 h60
  text "TID #:" at -1618.87,-1923.67 h60
  text "LAYER NAME =" at 805.63,-1929.49 h60
  text "010131" at -1972,-1930 h60
  text ".plot_File_Name" at 135,-2129 h35
  text "TEXAS INSTRUMENTS" at -4518.63,-2141.84 h60
  text ".Print_Time" at -3254.13,-2141.84 h60
  text ".Print_Date" at -2525.13,-2141.84 h60
  text "GENERATED    :" at -1655.63,-2141.84 h60
  text "PLOT NAME =" at 822.87,-2141.84 h60
M9 Title Sheet:
  drawing of 54 lines, arcs and shapes, not listed
  text "1" at -4683.29,6959.5 h70
  text "2" at -2187.63,6959.5 h70
  text "3" at 301.72,6959.5 h70
  text "4" at 2808.39,6959.5 h70
  text "5" at 5307.37,6959.5 h70
  text "6" at 7812.37,6959.5 h70
  text "A" at -5839.63,5816.5 h70
  text "A" at 8960.37,5816.5 h70
  text "B" at -5839.63,3436.5 h70
  text "B" at 8960.37,3436.5 h70
  text "C" at -5839.63,1061.5 h70
  text "C" at 8960.37,1061.5 h70
  text ".PRJ_Title" at 5970.37,-932.83 h70
  text "DESIGNED FOR:" at 5920.37,-1100.5 h45
  text ".PRJ_Customer" at 5970.37,-1240.5 h70
  text "D" at -5839.63,-1308.5 h70
  text "D" at 8960.37,-1308.5 h70
  text "FILE NAME:" at 5920.37,-1400.5 h45
  text ".PCB_File_Name_No_Path" at 5970.37,-1520.5 h60
  text "Texas Instruments (TI) and/or its licensors do not warrant the accuracy or completeness of this specification" at 950.87,-1682.34 h45
  text "ENGINEER:" at 5920.37,-1690.5 h45
  text "LAYOUT BY:" at 7425.37,-1690.5 h45
  text "or any information contained therein. TI and/or its licensors do not warrant that this design will meet" at 905.89,-1795 h45
  text ".PRJ_Engineer" at 5970.37,-1845.49 h70
  text ".PCB_Layout" at 7475.87,-1845.49 h70
  text "the specifications, will be suitable for your application or fit for any particular purpose, or will operate in" at 905.89,-1907.67 h45
  text "ALTIUM DESIGNER VERSION:" at 7425.37,-2000.5 h45
  text "an implementation. TI and/or its licensors do not warrant that the design is production worthy. You should" at 905.89,-2020.33 h45
  text "completely validate and test your design implementation to confirm the system functionality for your application." at 950.87,-2133 h45
  text ".print_Scale" at 5970.37,-2133.83 h70
  text ".Application_BuildNumber" at 7475.87,-2133.83 h70
  text "1" at -4683.29,-2340.5 h70
  text "2" at -2187.63,-2340.5 h70
  text "3" at 301.72,-2340.5 h70
  text "4" at 2808.39,-2340.5 h70
  text "5" at 5307.37,-2340.5 h70
  text "6" at 7812.37,-2340.5 h70
M10 Fab Notes:
  drawing of 252 lines, arcs and shapes, not listed
  text "IMPEDANCE TABLE:-" at -4340,6343 h60
  text "100 OHM DIFF" at -2372,6156 h50
  text "100 OHM DIFF" at -3208,6151 h50
  text "50 OHM SE" at -3810,6111 h50
  text "REFERENCE" at -1030,6110 h50
  text "LOOSELY COUPLED" at -2431,6080 h50
  text "TIGHTLY COUPLED" at -3267,6075 h50
  text "Layer" at -4364,5957 h50
  text "WIDTH/SPACING" at -2366,5955 h50
  text "TRACE WIDTH" at -3953,5951 h50
  text "WIDTH/SPACING" at -3202,5950 h50
  text "Layer" at -939,5882 h50
  text "(MILS)" at -2232,5849 h50
  text "(MILS)" at -3841,5845 h50
  text "(MILS)" at -3068,5844 h50
  text "+/-10%" at -2241,5762 h50
  text "+/-10%" at -3850,5758 h50
  text "+/-10%" at -3077,5757 h50
  text "DESIGN INFORMATION" at 6957.89,5733 h60
  text "L1_Top" at -4410.85,5642 h50
  text "6mil trace/" at -3182.26,5635 h50
  text "10mil trace/" at -2278.26,5628 h50
  text "L2_GND" at -1037.91,5609 h50
  text "11mils" at -3854,5591 h50
  text "(REFER ALSO ARRAY/PANEL PROFILING INFORMATION)" at 6596.33,5571.29 h60
  text "BOARD SIZE" at 5910.33,5567 h60
  text "Layer" at -4402,5552 h50
  text "5mil space" at -3180.26,5552 h50
  text "18mil space" at -2276.26,5545 h50
  text "60mm" at 7058.1,5443 h60
  text "X" at 6878.33,5439.18 h60
  text "73MM" at 6313.1,5433 h60
  text "L4_SIGNAL" at -4426.74,5420 h50
  text "5.5mil trace/" at -2304.26,5411 h50
  text "4.9mil trace/" at -3191.26,5406 h50
  text "L3_GND, L5_GND" at -1174,5375 h50
  text "Layer1" at -4373,5336 h50
  text "21.1mil space" at -2302.26,5328 h50
  text "7.1mil space" at -3189.26,5323 h50
  text "Number of Layers :" at 6313.33,5242 h60
  text "12" at 7408.15,5232 h60
  text "L6_SIGNAL" at -4456,5188 h50
  text "3.5mil trace/" at -3196.26,5186 h50
  text "3.75MILS" at -3869,5142 h50
  text "L5_GND, L7_GND" at -1179,5133 h50
  text "Layer2" at -4373,5109 h50
  text "3.5" at 7292,5107 h60
  text "6.5mil space" at -3194.26,5103 h50
  text "MIN. TRACK WIDTH:" at 6313.33,5103 h60
  text "MIL" at 7564.33,5103 h60
  text "5" at 7419,4977 h60
  text "MIN. CLEARANCE:" at 6313.33,4971 h60
  text "MIL" at 7564.33,4971 h60
  text "4mil trace/" at -3198.26,4954 h50
  text "L8_SIGNAL" at -4444,4947 h50
  text "L7_GND, L9_GND" at -1176,4913 h50
  text "4.25mils" at -3832,4909 h50
  text "6mil space" at -3196.26,4871 h50
  text "Layer3" at -4361,4868 h50
  text "18" at 7345,4847 h60
  text "MIN. VIA PAD SIZE:" at 6313.33,4839 h60
  text "MIL" at 7564.33,4839 h60
  text "5.5mil trace/" at -3187.26,4728 h50
  text "6.3mil trace/" at -2280.26,4726 h50
  text "L10_SIGNAL" at -4459,4721 h50
  text "5MIL" at 7008.33,4697.29 h60
  text "MINIMUM ANNULAR RING" at 5984.1,4693.01 h60
  text "EXTERNAL" at 7821.1,4693 h60
  text "6.5mils" at -3821,4683 h50
  text "L9_GND, L11_GND" at -1126,4683 h50
  text "6.7mil space" at -3185.26,4645 h50
  text "20.1mil space" at -2278.26,4643 h50
  text "Layer4" at -4351,4642 h50
  text "PER" at 6184.1,4575 h60
  text "IPC-D-275 CLASS 2 LEVEL C" at 6404.1,4575 h60
  text "L12_BOTTOM" at -4477.85,4505 h50
  text "10mil trace/" at -2302.26,4500 h50
  text "6mil trace/" at -3205.26,4489 h50
  text "MIL, HOLES" at 7892.33,4462.71 h60
  text "+/-" at 7499.87,4462 h60
  text "+/-" at 8353.87,4462 h60
  text "L11_GND" at -959.91,4460 h50
  text "REGISTRATION TOLERANCES:" at 5984.1,4457 h60
  text "METAL" at 7183.87,4457 h60
  text "5" at 7760.08,4457 h60
  text "3" at 8593.08,4457 h60
  text "MIL" at 8709.33,4457 h60
  text "11mils" at -3839,4444 h50
  text "Layer" at -4381,4418 h50
  text "18mil space" at -2300.26,4417 h50
  text "5mil space" at -3203.26,4406 h50
  text "MATERIAL:" at 5909.33,4247.54 h60
  text "R-5775K , R-5670K" at 8160,4110 h40
  text "FR-4 High Tg" at 6895.78,4107.21 h60
  text "X" at 7619,4107 h60
  text "FR-408" at 6330.34,4098.64 h60
  text "OTHER" at 7818.33,4098.64 h60
  text "63 MIL (1.6mm) +/-10%" at 6650.44,3935.92 h60
  text "THICKNESS:" at 5984.1,3931.64 h60
  text "X" at 6522.27,3931.64 h60
  text "OTHER" at 7935.33,3931.64 h60
  text "TOLERANCE:" at 5984.1,3773.64 h60
  text "X" at 6823.41,3773.64 h60
  text "ANSI IPC-6012 TYPE 3 CLASS 2" at 7010.35,3773.64 h60
  text "OTHER +/-" at 7010.33,3617.64 h60
  text "BOW & TWIST:" at 5984.1,3460.64 h60
  text "X" at 6823.41,3460.64 h60
  text "ANSI IPC-6012 TYPE 3 CLASS 2" at 7010.35,3460.64 h60
  text "OTHER +/-" at 7010.33,3302.13 h60
  text "COPPER THICKNESS (FINISHED):" at 5909.33,3166.64 h60
  text "1.2MIL (1oz)" at 6789.33,3013.92 h60
  text "2MIL (1.4oz)" at 7556.33,3013.92 h60
  text "2.8MIL (2oz)" at 8283.33,3013.92 h60
  text "OUTER:" at 6266.33,3009.64 h60
  text "X" at 7427.33,3007.64 h60
  text "X" at 6657.33,2859.64 h60
  text "0.6MIL" at 6789.33,2856.92 h60
  text "2.8MIL (2oz)" at 7556.33,2856.92 h60
  text "N/A" at 8282.87,2857.29 h60
  text "INNER SIGNAL:" at 5977.25,2852.64 h60
  text "DRILLING:" at 5909.33,2713.64 h60
  text "REFERENCE:" at 5984.1,2596.64 h60
  text "X" at 6632.33,2596.64 h60
  text "AS SHOWN" at 6819.33,2596.64 h60
  text "X" at 7533.33,2596.64 h60
  text "NC_DRILL FILES" at 7670.33,2596.64 h60
  text "PTH MIN COPPER THICKNESS:" at 5984.1,2438.64 h60
  text "X" at 7334.33,2438.64 h60
  text "1MIL" at 7471.33,2438.64 h60
  text "OTHER" at 7968.33,2438.64 h60
  text "BOARD FINISH:" at 5909.33,2279.64 h60
  text "SILKSCREEN:" at 6064.56,2161.64 h60
  text "X" at 7013.33,2161.64 h60
  text "TOP" at 7139.33,2161.64 h60
  text "X" at 7523.33,2161.64 h60
  text "BOTTOM" at 7650.33,2161.64 h60
  text "SILKSCREEN COLOR:" at 6064.56,1994.64 h60
  text "X" at 7012.29,1994.64 h60
  text "WHITE" at 7139.33,1994.64 h60
  text "OTHER" at 7650.33,1994.64 h60
  text "SOLDER RESIST COLOR:" at 6064.56,1824.64 h60
  text "X" at 6632.3,1665.44 h60
  text "GREEN" at 6759.33,1665.44 h60
  text "BLUE" at 7350.33,1665.44 h60
  text "OTHER" at 7888.33,1665.44 h60
  text "IMMERSION GOLD (ENIG)" at 6970.33,1476.92 h60
  text "ENEPIG" at 8307.87,1473.64 h60
  text "SURFACE FINISH:" at 5909.33,1472.64 h60
  text "X" at 6783.39,1472.64 h60
  text "IMM. TIN/SILVER OR EQUIV" at 6238.87,1315.64 h60
  text "OTHER" at 7670.33,1315.64 h60
  text "ARRAY/PANEL:" at 5909.33,1136.64 h60
  text "CUT AND TRIM PER MECH LAYER 1" at 6970.33,1132.35 h60
  text "N.C. ROUTE" at 6970.33,980.64 h60
  text "X" at 7649.33,980.64 h60
  text "V. SCORE" at 7836.33,980.64 h60
  text "CERTIFICATION:" at 5909.33,843.64 h60
  text "MATERIALS AND WORKMANSHIP FOR ALL PCBS" at 6634.33,843.64 h60
  text "TO MEET OR EXCEED THE REQUIREMENTS OF:" at 6634.33,745.64 h60
  text "X" at 6260.84,609.14 h60
  text "ANSI IPC-A-600F CLASS ->" at 6399.84,609.14 h60
  text "X" at 8038.89,609.14 h60
  text "2" at 8157.84,609.14 h60
  text "1" at 7842.84,607.64 h60
  text "3" at 8511.84,607.64 h60
  text "X" at 6262.89,449.64 h60
  text "UL 94V-0" at 6399.84,449.64 h60
  text "X" at 7074.89,449.64 h60
  text "RoHS" at 7211.84,449.64 h60
  text "OTHER" at 7856.24,449.64 h60
  text "PER ORDER" at 8253.3,449.64 h60
  text "X" at 8214.09,315 h60
  text "ADDITIONAL REQUIREMENTS:" at 5909.33,308.64 h60
  text "VIA TENTING:" at 7126.87,308 h60
  text "YES" at 7676.54,298.92 h60
  text "NO" at 8041.35,293.69 h60
  text "MICROSECTION:" at 5984.1,193.64 h60
  text "YES" at 6889.84,193.64 h60
  text "X" at 8359.09,185 h60
  text "IMPEDANCE CONTROL:" at 7152.87,184 h60
  text "YES" at 8136.87,183 h60
  text "NO" at 8512.35,165.69 h60
  text "REQUIRED" at 7751.33,37.5 h60
  text "BARE BOARD ELEC. TEST:" at 5984.1,34.64 h60
  text "NONE" at 7289.84,34.64 h60
  text "X" at 7624.33,34.64 h60
  text "PER ORDER" at 8343.33,34.64 h60
  text "MANUFACTURER'S UL:" at 5984.1,-122.36 h60
  text "RAIL" at 7149.84,-126.65 h60
  text "METAL" at 7641.65,-126.65 h60
  text "X" at 8016.87,-127 h60
  text "SILK" at 8153.33,-126.65 h60
M11 Gerber Information:
  lines w10: -5715.13,-2007.17 884.87,-2007.17 ; -5715.13,-1803.83 886.87,-1803.83 ; -5715.13,-1600.5 -5715.13,-2210.5 -1710.13,-2210.5 886.87,-2210.5 886.87,-1600.5 -5714.63,-1600.5 -5714.63,-2210.5 -4139.13,-2210.5 ; -3250.13,-2210.5 -3250.13,-1600.5 ; -1983.13,-1803.83 -1983.13,-1600.5 ; -1143.13,-1803.83 -1143.13,-1600.5 ; -521.13,-2217 -521.13,-2014.17
  text "ALL ARTWORK VIEWED FROM TOP SIDE" at -5651.63,-1732.67 h60
  text "BOARD #:" at -3175.13,-1732.67 h60
  text "REV:" at -1785.13,-1732.67 h60
  text "SVN REV:" at -947.13,-1732.67 h60
  text "'.PCB_Rev'" at -1512,-1735 h60
  text "'.PRJ_Title'" at -2677,-1740 h60
  text "TID #:" at -3175.13,-1928.67 h60
  text "'.TID'" at -2822,-1935 h60
  text "LAYER NAME =" at -5650.63,-1936.49 h60
  text "PLOT NAME =" at -5651.63,-2141.34 h60
  text ".plot_File_Name" at -4846.13,-2141.34 h30
  text "GENERATED    :" at -3173.13,-2141.34 h60
  text ".Print_Date" at -2303.63,-2141.34 h60
  text ".Print_Time" at -1574.63,-2141.34 h60
  text "TEXAS INSTRUMENTS" at -310.13,-2141.34 h60
M12 Stackup:
  drawing of 711 lines, arcs and shapes, not listed
  text "Layer" at -5345.5,3129.5 h60
  text "Name" at -4935.59,3129.5 h60
  text "Material" at -3825.9,3129.5 h60
  text "Thickness" at -2966.13,3129.5 h60
  text "Constant" at -2316.3,3129.5 h60
  text "Board Layer Stack" at -1746.44,3129.5 h60
  text "1" at -5345.5,3009.5 h60
  text "Top Overlay" at -4935.59,3009.5 h60
  text "2" at -5345.5,2889.5 h60
  text "Top Solder" at -4935.59,2889.5 h60
  text "Solder Resist" at -3825.9,2889.5 h60
  text "0.40mil" at -2966.13,2889.5 h60
  text "3.5" at -2316.3,2889.5 h60
  text "3" at -5345.5,2769.5 h60
  text "L1_Top Layer" at -4935.59,2769.5 h60
  text "Copper" at -3825.9,2769.5 h60
  text "2.00mil" at -2966.13,2769.5 h60
  text "4" at -5345.5,2649.5 h60
  text "Dielectric1" at -4935.59,2649.5 h60
  text "R-5670K" at -3825.9,2649.5 h60
  text "5.60mil" at -2966.13,2649.5 h60
  text "3.22" at -2316.3,2649.5 h60
  text "5" at -5345.5,2529.5 h60
  text "L2_GND" at -4935.59,2529.5 h60
  text "Copper" at -3825.9,2529.5 h60
  text "0.60mil" at -2966.13,2529.5 h60
  text "6" at -5345.5,2409.5 h60
  text "Dielectric 2" at -4935.59,2409.5 h60
  text "R-5775K" at -3825.9,2409.5 h60
  text "5.00mil" at -2966.13,2409.5 h60
  text "3.58" at -2316.3,2409.5 h60
  text "7" at -5345.5,2289.5 h60
  text "L3_GND" at -4935.59,2289.5 h60
  text "Copper" at -3825.9,2289.5 h60
  text "0.60mil" at -2966.13,2289.5 h60
  text "8" at -5345.5,2169.5 h60
  text "Dielectric 3" at -4935.59,2169.5 h60
  text "R-5670K" at -3825.9,2169.5 h60
  text "7.50mil" at -2966.13,2169.5 h60
  text "3.23" at -2316.3,2169.5 h60
  text "9" at -5345.5,2049.5 h60
  text "L4_Signal layer1" at -4935.59,2049.5 h60
  text "Copper" at -3825.9,2049.5 h60
  text "0.60mil" at -2966.13,2049.5 h60
  text "10" at -5345.5,1929.5 h60
  text "Dielectric 4" at -4935.59,1929.5 h60
  text "R-5775K" at -3825.9,1929.5 h60
  text "4.00mil" at -2966.13,1929.5 h60
  text "3.39" at -2316.3,1929.5 h60
  text "11" at -5345.5,1809.5 h60
  text "L5_GND" at -4935.59,1809.5 h60
  text "Copper" at -3825.9,1809.5 h60
  text "0.60mil" at -2966.13,1809.5 h60
  text "12" at -5345.5,1689.5 h60
  text "Dielectric 5" at -4935.59,1689.5 h60
  text "R-5670K" at -3825.9,1689.5 h60
  text "4.20mil" at -2966.13,1689.5 h60
  text "3.18" at -2316.3,1689.5 h60
  text "13" at -5345.5,1569.5 h60
  text "L6_Signal Layer2" at -4935.59,1569.5 h60
  text "Copper" at -3825.9,1569.5 h60
  text "0.60mil" at -2966.13,1569.5 h60
  text "14" at -5345.5,1449.5 h60
  text "Dielectric 6" at -4935.59,1449.5 h60
  text "R-5775K" at -3825.9,1449.5 h60
  text "3.00mil" at -2966.13,1449.5 h60
  text "3.42" at -2316.3,1449.5 h60
  text "15" at -5345.5,1329.5 h60
  text "L7_GND" at -4935.59,1329.5 h60
  text "Copper" at -3825.9,1329.5 h60
  text "0.60mil" at -2966.13,1329.5 h60
  text "16" at -5345.5,1209.5 h60
  text "Dielectric 7" at -4935.59,1209.5 h60
  text "R-5670K" at -3825.9,1209.5 h60
  text "4.20mil" at -2966.13,1209.5 h60
  text "3.18" at -2316.3,1209.5 h60
  text "17" at -5345.5,1089.5 h60
  text "L8_Signal Layer3" at -4935.59,1089.5 h60
  text "Copper" at -3825.9,1089.5 h60
  text "0.60mil" at -2966.13,1089.5 h60
  text "18" at -5345.5,969.5 h60
  text "Dielectric 8" at -4935.59,969.5 h60
  text "R-5775K" at -3825.9,969.5 h60
  text "4.00mil" at -2966.13,969.5 h60
  text "3.39" at -2316.3,969.5 h60
  text "19" at -5345.5,849.5 h60
  text "L9_GND" at -4935.59,849.5 h60
  text "Copper" at -3825.9,849.5 h60
  text "0.60mil" at -2966.13,849.5 h60
  text "20" at -5345.5,729.5 h60
  text "Dielectric 9" at -4935.59,729.5 h60
  text "R-5670K" at -3825.9,729.5 h60
  text "7.50mil" at -2966.13,729.5 h60
  text "3.23" at -2316.3,729.5 h60
  text "21" at -5345.5,609.5 h60
  text "L10_Signal Layer4" at -4935.59,609.5 h60
  text "Copper" at -3825.9,609.5 h60
  text "0.60mil" at -2966.13,609.5 h60
  text "22" at -5345.5,489.5 h60
  text "Dielectric 10" at -4935.59,489.5 h60
  text "R-5775K" at -3825.9,489.5 h60
  text "5.00mil" at -2966.13,489.5 h60
  text "3.58" at -2316.3,489.5 h60
  text "23" at -5345.5,369.5 h60
  text "L11_GND" at -4935.59,369.5 h60
  text "Copper" at -3825.9,369.5 h60
  text "0.60mil" at -2966.13,369.5 h60
  text "24" at -5345.5,249.5 h60
  text "Dielectric 11" at -4935.59,249.5 h60
  text "R-5670K" at -3825.9,249.5 h60
  text "5.60mil" at -2966.13,249.5 h60
  text "3.22" at -2316.3,249.5 h60
  text "25" at -5345.5,129.5 h60
  text "L12_Bottom Layer" at -4935.59,129.5 h60
  text "Copper" at -3825.9,129.5 h60
  text "2.00mil" at -2966.13,129.5 h60
  text "26" at -5345.5,9.5 h60
  text "Bottom Solder" at -4935.59,9.5 h60
  text "Solder Resist" at -3825.9,9.5 h60
  text "0.40mil" at -2966.13,9.5 h60
  text "3.5" at -2316.3,9.5 h60
  text "27" at -5345.5,-110.5 h60
  text "Bottom Overlay" at -4935.59,-110.5 h60
M13 Component Bodies Top:
  text ".Layer_Name" at -4846.13,-1935.49 h60
M14 Component Bodies Bottom:
  text ".Layer_Name" at -4846.13,-1935.49 h60
M15 Courtyards Top:
  text ".Layer_Name" at -4846.13,-1935.49 h60
M16 Courtyards Bottom:
  text ".Layer_Name" at -4846.13,-1935.49 h60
